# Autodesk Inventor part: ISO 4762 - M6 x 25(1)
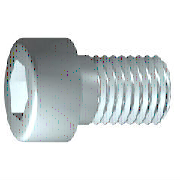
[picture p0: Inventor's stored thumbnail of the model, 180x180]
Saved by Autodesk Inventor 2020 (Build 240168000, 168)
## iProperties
Created: 2019-01
Part Number: ISO 4762 - M6 x 25(1)
Material: Nerezová ocel 440C
Description: Šroub s válcovou hlavou s vnitřním šestihranem
Document SubType Name: Modeling
Standard: ISO 4762
Designer: doma
Standard Revision: Fourth edition 2004-03-01
Standards Organization: ISO
Language: cs-CZ
Size Designation: M6 x 25
Categories: <MemberInstance><Categories><Category DisplayName="Spojovací materiál" InternalName="e4da775c-781d-43d5-af7c-5136215cf5a6" Mnemonic="FSTN"><Category DisplayName
Density: 7.75 g/cm^3
Appearance: Pololeštěná
IsCustomPart: 0
Author: doma
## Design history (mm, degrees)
sketch "Náčrt1"
  geometry: L1 (-1.333, 0)-(25, 0); L2 (25, 0)-(25, 3); L3 (25, 3)-(2.5, 3); L4 (2.5, 3)-(1.886, 3); L5 (1.886, 3)-(0, 3); L6 (0, 3)-(0, 5); L7 (0, 5)-(-6, 5); L8 (-6, 5)-(-6, 2.887); L9 (-6, 2.887)-(-3, 2.887); L10 (-3, 2.887)-(-1.333, 0); L11 (-12.2, 0)-(31.2, 0) reference; L12 (0, -1)-(0, 6) reference; L13 (2.5, 3)-(0, 3)
  constraints: 22 end point, 6 parallel, 2 collinear, 2 perpendicular, 1 horizontal, 1 point on line
  dimensions: "d1" = 22.5 distance from line of L3.end L2 (= GEL); "d2" = 0.61355 distance of L4.end L3.end (computed from GAL); "d3" = 6 distance between parallel lines of L8 L6 (= KOH); "d4" = 3 distance of L8.end L9.end (= INTI); "d5" = 60 deg angle of L10 L1; "d6" = 6 diameter of L3 L1 (= GD); "d7" = 6 diameter of L5 L1 (= BDM); "d8" = 5.7735 diameter of L9 L1 (= 1.1547 x SW); "d9" = 10 diameter of L7 L1 (= KOD); "d26" = 25 distance between parallel lines of L12 L2 (= NLG)
revolve "Těleso" sketch "Náčrt1" stored, may be unused: angle "d10" = 90 deg
sketch "Náčrt2"
  geometry: L1 (0, -7)-(0, 7) reference; L2 (-7, 0)-(7, 0) reference; L3 (2.887, 0)-(1.443, -2.5); L4 (1.443, -2.5)-(-1.443, -2.5); L5 (-1.443, -2.5)-(-2.887, 0); L6 (-2.887, 0)-(-1.443, 2.5); L7 (-1.443, 2.5)-(1.443, 2.5); L8 (1.443, 2.5)-(2.887, 0); 2 further points
  constraints: 12 end point, 1 coincident, 1 horizontal alignment, 1 point on line, 12 other
extrude "Drážka" join sketch "Náčrt2" stored distance "d11" = 10; taper "d12" = 0 deg
workplane "Work Plane1"
fillet "Fillet2" dims "d30" = 0.1 (= R)
body "Solid1"
fillet "Zaoblení1" dims "d17" = 0.6 (= RR)
feature "Závit" dims "d13" = 22.5 (= GEL), "d14" = 0
chamfer "Zkosení1" distance "d15" = 0.61345 (= -0.5 x SPD + 0.5 x GD); stored, may be unused: second distance "d16" = 0.61345 (= GUL), angle "d27" = 45 deg
other parameters: "GD" = 6 [user parameter; used in 2 equation terms], "NLG" = 25 [user parameter; used in 1 equation term], "GEL" = 22.5 [user parameter; used in 2 equation terms], "KOD" = 10 [user parameter; used in 1 equation term], "KOH" = 6 [user parameter; used in 1 equation term], "INTI" = 3 [user parameter; used in 1 equation term], "GAL" = 0.61345 (= 0.61345 x PTC) [user parameter; used in 1 equation term], "GUL" = 0.61345 (= 0.61345 x PTC) [user parameter; used in 1 equation term], "BDM" = 6 (= NND) [user parameter; used in 1 equation term], "SW" = 5 [user parameter; used in 2 equation terms], "RR" = 0.6 [user parameter; used in 1 equation term], "SPD" = 4.7731 (= NND - 1.2269 x PTC) [user parameter; used in 1 equation term], "d19" = 0, "d28" = 0, "d29" = 0, "R" = 0.1 [user parameter; used in 1 equation term], "TOA" = 30 deg [user parameter], "GD1" = 4.7731 (= THREADDIA - 1.2269 x PTC) [user parameter], "THREADDIA" = 6 [user parameter; used in 1 equation term], "FAWI" = 45 deg [user parameter], "PTC" = 1 [user parameter; used in 5 equation terms], "NND" = 6 [user parameter; used in 2 equation terms], "E0" = 5.775 (= 1.155 x SW) [user parameter]
